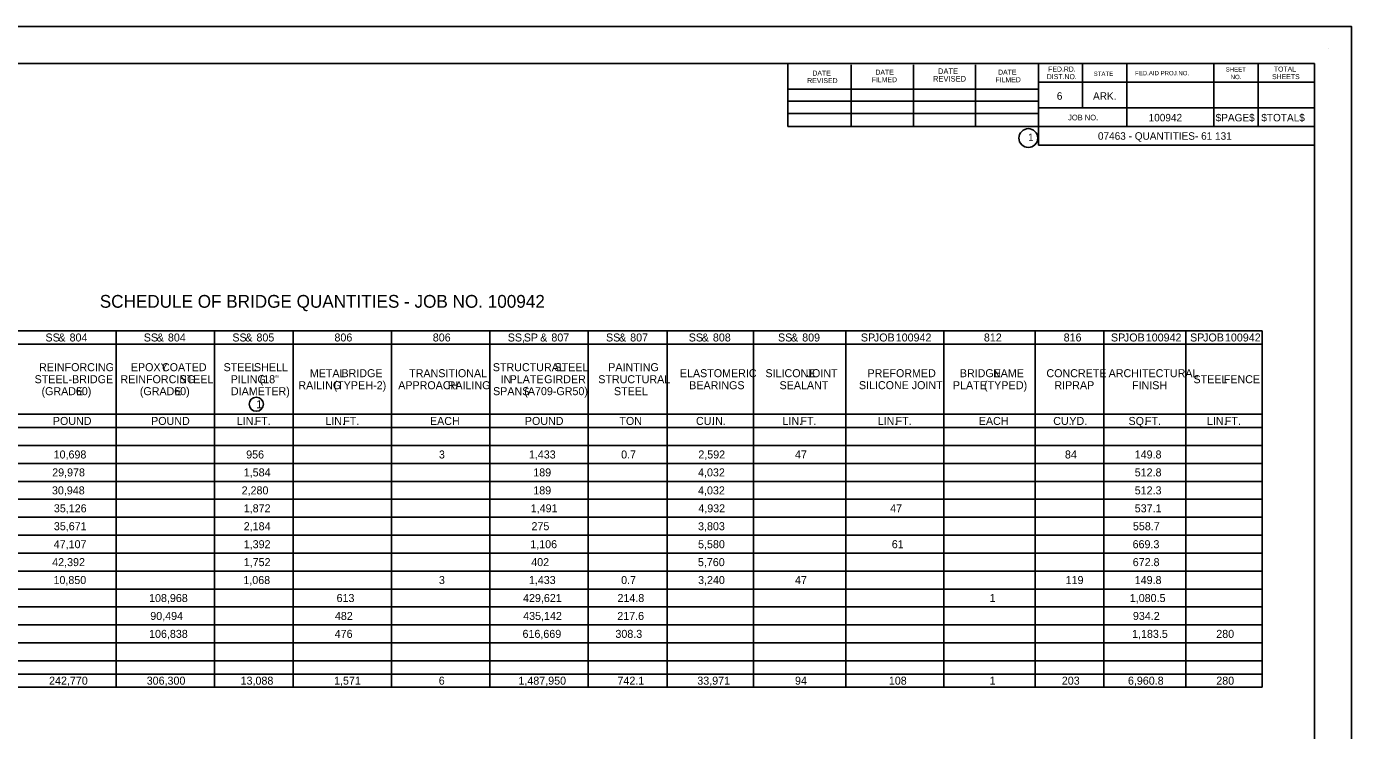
# Model space of a CAD drawing. Extents: x -129 to 14744569, y -102 to 1829048.
# Drawn here: x -115.83 to -95.13, y -90.98 to -79.98 of the extents above; entities that cross this region are included whole.
import ezdxf

# ---------------------------------------------------------------- set-up
doc = ezdxf.new("R2010")
doc.units = 0
for name, color, linetype in [('B_Copy In', 7, 'Continuous'), ('B_Dimensions', 7, 'Continuous'), ('B_Text', 7, 'Continuous'), ('B_Title Text', 7, 'Continuous'), ('R_Border', 7, 'Continuous')]:
    doc.layers.add(name, color=color, linetype=linetype)

msp = doc.modelspace()

# ---------------------------------------------------------------- linework, layer by layer
at = {"layer": 'B_Text'}
msp.add_circle((-112.242, -85.881), 0.11, dxfattribs=at)
at = {"layer": 'B_Title Text'}
for p, q in [((-127.044, -84.735), (-96.527, -84.735)), ((-114.43, -90.304), (-114.43, -84.735)), ((-112.895, -90.304), (-112.895, -84.735)), ((-111.664, -90.304), (-111.664, -84.735)), ((-110.128, -90.304), (-110.128, -84.735)), ((-108.593, -90.304), (-108.593, -84.735)), ((-107.057, -90.304), (-107.057, -84.735)), ((-105.826, -90.304), (-105.826, -84.735)), ((-104.473, -90.304), (-104.473, -84.735)), ((-103.035, -90.304), (-103.035, -84.735)), ((-101.5, -90.304), (-101.5, -84.735)), ((-100.074, -90.304), (-100.074, -84.735)), ((-99.001, -90.304), (-99.001, -84.735)), ((-97.721, -90.304), (-97.721, -84.735)), ((-96.527, -90.304), (-96.527, -84.735)), ((-123.071, -84.942), (-96.527, -84.942)), ((-103.035, -86.039), (-103.035, -84.942)), ((-101.5, -86.039), (-101.5, -84.942)), ((-123.071, -86.039), (-96.527, -86.039)), ((-103.035, -86.039), (-101.5, -86.039)), ((-101.5, -86.039), (-96.527, -86.039)), ((-127.044, -86.246), (-96.527, -86.246)), ((-125.485, -86.526), (-96.527, -86.526)), ((-125.485, -86.807), (-96.527, -86.807)), ((-125.485, -87.087), (-96.527, -87.087)), ((-125.485, -87.367), (-96.527, -87.367)), ((-125.485, -87.648), (-96.527, -87.648)), ((-125.485, -87.928), (-96.527, -87.928)), ((-125.485, -88.208), (-96.527, -88.208)), ((-125.485, -88.489), (-96.527, -88.489)), ((-125.485, -88.769), (-96.527, -88.769)), ((-125.485, -89.049), (-96.527, -89.049)), ((-125.485, -89.329), (-96.527, -89.329)), ((-125.485, -89.61), (-96.527, -89.61)), ((-127.044, -89.89), (-96.527, -89.89)), ((-127.044, -90.097), (-96.527, -90.097)), ((-127.044, -90.304), (-96.527, -90.304))]:
    msp.add_line(p, q, dxfattribs=at)
at = {"layer": 'R_Border'}
for p, q in [((-95.492, -80.326), (-95.492, -80.326)), ((-127.618, -80.556), (-95.711, -80.556)), ((-103.937, -81.544), (-103.937, -80.556)), ((-102.951, -81.544), (-102.951, -80.576)), ((-101.975, -81.544), (-101.975, -80.576)), ((-101.007, -81.544), (-101.007, -80.576)), ((-100.021, -80.556), (-100.021, -81.836)), ((-99.337, -80.556), (-99.337, -81.25)), ((-98.643, -80.556), (-98.643, -81.544)), ((-97.285, -80.556), (-97.285, -81.544)), ((-96.591, -80.556), (-96.591, -81.544)), ((-95.711, -101.403), (-95.711, -80.556)), ((-95.711, -80.85), (-100.021, -80.85)), ((-95.711, -80.848), (-95.711, -80.848)), ((-103.937, -80.958), (-100.021, -80.958)), ((-103.937, -81.144), (-100.021, -81.144)), ((-103.937, -81.544), (-103.937, -81.338)), ((-103.937, -81.338), (-100.021, -81.338)), ((-95.711, -81.25), (-100.021, -81.25)), ((-99.725, -81.25), (-95.711, -81.25)), ((-95.711, -81.544), (-103.937, -81.544)), ((-100.021, -81.836), (-95.711, -81.836))]:
    msp.add_line(p, q, dxfattribs=at)
msp.add_lwpolyline([(-129.134, -79.979), (-95.134, -79.979), (-95.134, -101.979), (-129.134, -101.979)], close=True, dxfattribs=at)
msp.add_circle((-100.182, -81.722), 0.147, dxfattribs=at)

# ---------------------------------------------------------------- texts
at = {"layer": 'B_Copy In'}
msp.add_text('07463 - QUANTITIES- 61 131', height=0.11724, dxfattribs=at).set_placement((-99.095, -81.749))
at = {"layer": 'B_Dimensions'}
msp.add_text('1', height=0.125, rotation=360, dxfattribs=at).set_placement((-112.242, -85.944))
at = {"layer": 'B_Text'}
for s, height, p in [('SS', 0.125, (-115.535, -84.901)), (' &', 0.125, (-115.38, -84.901)), (' 804', 0.125, (-115.205, -84.901)), ('SS', 0.125, (-114, -84.901)), (' &', 0.125, (-113.844, -84.901)), (' 804', 0.125, (-113.669, -84.901)), ('SS', 0.125, (-112.616, -84.901)), (' &', 0.125, (-112.461, -84.901)), (' 805', 0.125, (-112.286, -84.901)), ('806', 0.125, (-111.021, -84.901)), ('806', 0.125, (-109.485, -84.901)), ('SS,', 0.125, (-108.314, -84.901)), (' SP', 0.125, (-108.11, -84.901)), (' &', 0.125, (-107.854, -84.901)), (' 807', 0.125, (-107.679, -84.901)), ('SS', 0.125, (-106.779, -84.901)), (' &', 0.125, (-106.623, -84.901)), (' 807', 0.125, (-106.448, -84.901)), ('SS', 0.125, (-105.487, -84.901)), (' &', 0.125, (-105.331, -84.901)), (' 808', 0.125, (-105.156, -84.901)), ('SS', 0.125, (-104.092, -84.901)), (' &', 0.125, (-103.936, -84.901)), (' 809', 0.125, (-103.761, -84.901)), ('SP', 0.125, (-102.798, -84.901)), (' JOB', 0.125, (-102.641, -84.901)), (' 100942', 0.125, (-102.3, -84.901)), ('812', 0.125, (-100.876, -84.901)), ('816', 0.125, (-99.63, -84.901)), ('SP', 0.125, (-98.892, -84.901)), (' JOB', 0.125, (-98.735, -84.901)), (' 100942', 0.125, (-98.394, -84.901)), ('SP', 0.125, (-97.655, -84.901)), (' JOB', 0.125, (-97.498, -84.901)), (' 100942', 0.125, (-97.157, -84.901)), ('REINFORCING', 0.125, (-115.636, -85.365)), ('EPOXY', 0.125, (-114.202, -85.365)), (' COATED', 0.125, (-113.762, -85.365)), ('STEEL', 0.125, (-112.753, -85.365)), (' SHELL', 0.125, (-112.325, -85.365)), ('STRUCTURAL', 0.125, (-108.547, -85.365)), (' STEEL', 0.125, (-107.63, -85.365)), ('PAINTING', 0.125, (-106.744, -85.365)), ('STEEL-BRIDGE', 0.125, (-115.705, -85.553)), ('REINFORCING', 0.125, (-114.364, -85.553)), (' STEEL', 0.125, (-113.488, -85.553)), ('PILING', 0.125, (-112.642, -85.553)), (' (18"', 0.125, (-112.236, -85.553)), ('METAL', 0.125, (-111.406, -85.459)), (' BRIDGE', 0.125, (-110.958, -85.459)), ('TRANSITIONAL', 0.125, (-109.854, -85.459)), ('IN', 0.125, (-108.426, -85.553)), (' PLATE', 0.125, (-108.331, -85.553)), (' GIRDER', 0.125, (-107.791, -85.553)), ('STRUCTURAL', 0.125, (-106.9, -85.553)), ('ELASTOMERIC', 0.125, (-105.625, -85.459)), ('SILICONE', 0.125, (-104.288, -85.459)), (' JOINT', 0.125, (-103.691, -85.459)), ('PREFORMED ', 0.1248, (-102.694, -85.459)), ('BRIDGE', 0.125, (-101.252, -85.459)), (' NAME', 0.125, (-100.781, -85.459)), ('CONCRETE', 0.125, (-99.899, -85.459)), ('ARCHITECTURAL', 0.125, (-98.927, -85.459)), ('STEEL', 0.125, (-97.602, -85.553)), (' FENCE', 0.125, (-97.175, -85.553)), ('(GRADE', 0.125, (-115.597, -85.74)), (' 60)', 0.125, (-115.107, -85.74)), ('(GRADE', 0.125, (-114.061, -85.74)), (' 60)', 0.125, (-113.571, -85.74)), ('DIAMETER)', 0.125, (-112.638, -85.74)), ('RAILING', 0.125, (-111.585, -85.647)), (' (TYPE', 0.125, (-111.081, -85.647)), (' H-2)', 0.125, (-110.584, -85.647)), ('APPROACH', 0.125, (-110.025, -85.647)), (' RAILING', 0.125, (-109.299, -85.647)), ('SPANS', 0.125, (-108.543, -85.74)), (' (A709-GR50)', 0.125, (-108.102, -85.74)), ('STEEL', 0.125, (-106.655, -85.74)), ('BEARINGS', 0.125, (-105.479, -85.647)), ('SEALANT', 0.125, (-104.068, -85.647)), ('SILICONE JOINT', 0.1248, (-102.828, -85.646)), ('PLATE', 0.125, (-101.36, -85.647)), (' (TYPE', 0.125, (-100.92, -85.647)), (' D)', 0.125, (-100.423, -85.647)), ('RIPRAP', 0.125, (-99.775, -85.647)), ('FINISH', 0.125, (-98.562, -85.647)), ('POUND', 0.125, (-115.42, -86.205)), ('POUND', 0.125, (-113.885, -86.205)), ('LIN.', 0.125, (-112.547, -86.205)), (' FT.', 0.125, (-112.314, -86.205)), ('LIN.', 0.125, (-111.164, -86.205)), (' FT.', 0.125, (-110.931, -86.205)), ('EACH', 0.125, (-109.529, -86.205)), ('POUND', 0.125, (-108.047, -86.205)), ('TON', 0.125, (-106.57, -86.205)), ('CU.', 0.125, (-105.374, -86.205)), (' IN.', 0.125, (-105.168, -86.205)), ('LIN.', 0.125, (-104.022, -86.205)), (' FT.', 0.125, (-103.789, -86.205)), ('LIN.', 0.125, (-102.535, -86.205)), (' FT.', 0.125, (-102.302, -86.205)), ('EACH', 0.125, (-100.956, -86.205)), ('CU.', 0.125, (-99.793, -86.205)), (' YD.', 0.125, (-99.587, -86.205)), ('SQ.', 0.125, (-98.617, -86.205)), (' FT.', 0.125, (-98.408, -86.205)), ('LIN.', 0.125, (-97.392, -86.205)), (' FT.', 0.125, (-97.159, -86.205)), ('10,698', 0.125, (-115.408, -86.729)), ('956', 0.125, (-112.4, -86.729)), ('3', 0.125, (-109.389, -86.729)), ('1,433', 0.125, (-107.984, -86.729)), ('0.7', 0.125, (-106.543, -86.729)), ('2,592', 0.125, (-105.337, -86.729)), ('47', 0.125, (-103.827, -86.729)), ('84', 0.125, (-99.61, -86.729)), ('149.8', 0.125, (-98.52, -86.729)), ('29,978', 0.125, (-115.43, -87.009)), ('1,584', 0.125, (-112.438, -87.009)), ('189', 0.125, (-107.915, -87.009)), ('4,032', 0.125, (-105.341, -87.009)), ('512.8', 0.125, (-98.52, -87.009)), ('30,948', 0.125, (-115.434, -87.29)), ('2,280', 0.125, (-112.471, -87.29)), ('189', 0.125, (-107.915, -87.29)), ('4,032', 0.125, (-105.341, -87.29)), ('512.3', 0.125, (-98.52, -87.29)), ('35,126', 0.125, (-115.404, -87.57)), ('1,872', 0.125, (-112.438, -87.57)), ('1,491', 0.125, (-107.955, -87.57)), ('4,932', 0.125, (-105.337, -87.57)), ('47', 0.125, (-102.34, -87.57)), ('537.1', 0.125, (-98.52, -87.57)), ('35,671', 0.125, (-115.404, -87.85)), ('2,184', 0.125, (-112.438, -87.85)), ('275', 0.125, (-107.943, -87.85)), ('3,803', 0.125, (-105.341, -87.85)), ('558.7', 0.125, (-98.548, -87.85)), ('47,107', 0.125, (-115.406, -88.131)), ('1,392', 0.125, (-112.438, -88.131)), ('1,106', 0.125, (-107.962, -88.131)), ('5,580', 0.125, (-105.341, -88.131)), ('61', 0.125, (-102.315, -88.131)), ('669.3', 0.125, (-98.553, -88.131)), ('42,392', 0.125, (-115.43, -88.411)), ('1,752', 0.125, (-112.438, -88.411)), ('402', 0.125, (-107.947, -88.411)), ('5,760', 0.125, (-105.343, -88.411)), ('672.8', 0.125, (-98.551, -88.411)), ('10,850', 0.125, (-115.41, -88.691)), ('1,068', 0.125, (-112.444, -88.691)), ('3', 0.125, (-109.389, -88.691)), ('1,433', 0.125, (-107.984, -88.691)), ('0.7', 0.125, (-106.543, -88.691)), ('3,240', 0.125, (-105.341, -88.691)), ('47', 0.125, (-103.827, -88.691)), ('119', 0.125, (-99.599, -88.691)), ('149.8', 0.125, (-98.52, -88.691)), ('108,968', 0.125, (-113.917, -88.972)), ('613', 0.125, (-110.988, -88.972)), ('429,621', 0.125, (-108.075, -88.972)), ('214.8', 0.125, (-106.6, -88.972)), ('1', 0.125, (-100.787, -88.972)), ('1,080.5', 0.125, (-98.597, -88.972)), ('90,494', 0.125, (-113.898, -89.252)), ('482', 0.125, (-111.014, -89.252)), ('435,142', 0.125, (-108.073, -89.252)), ('217.6', 0.125, (-106.603, -89.252)), ('934.2', 0.125, (-98.548, -89.252)), ('106,838', 0.125, (-113.917, -89.532)), ('476', 0.125, (-111.017, -89.532)), ('616,669', 0.125, (-108.083, -89.532)), ('308.3', 0.125, (-106.632, -89.532)), ('1,183.5', 0.125, (-98.561, -89.532)), ('280', 0.125, (-97.246, -89.532)), ('242,770', 0.125, (-115.479, -90.263)), ('306,300', 0.125, (-113.954, -90.263)), ('13,088', 0.125, (-112.487, -90.263)), ('1,571', 0.125, (-111.027, -90.263)), ('6', 0.125, (-109.392, -90.263)), ('1,487,950', 0.125, (-108.147, -90.263)), ('742.1', 0.125, (-106.6, -90.263)), ('33,971', 0.125, (-105.353, -90.263)), ('94', 0.125, (-103.827, -90.263)), ('108', 0.125, (-102.361, -90.263)), ('1', 0.125, (-100.787, -90.263)), ('203', 0.125, (-99.659, -90.263)), ('6,960.8', 0.125, (-98.626, -90.263)), ('280', 0.125, (-97.246, -90.263))]:
    msp.add_text(s, height=height, dxfattribs=at).set_placement(p)
at = {"layer": 'B_Title Text'}
msp.add_text('SCHEDULE OF BRIDGE QUANTITIES - JOB NO. 100942', height=0.19992, dxfattribs=at).set_placement((-114.687, -84.374))
at = {"layer": 'R_Border'}
for s, height, p in [('DATE', 0.0782, (-103.555, -80.747)), ('DATE', 0.0782, (-102.571, -80.732)), ('DATE', 0.0879, (-101.593, -80.722)), ('DATE', 0.0782, (-100.655, -80.732)), ('FED.RD.', 0.0782, (-99.873, -80.684)), ('STATE', 0.0684, (-99.161, -80.752)), ('FED.AID PROJ.NO.', 0.0684, (-98.515, -80.742)), ('SHEET', 0.0684, (-97.099, -80.684)), ('TOTAL', 0.0782, (-96.347, -80.684)), ('REVISED', 0.0782, (-103.636, -80.864)), ('FILMED', 0.0782, (-102.629, -80.85)), ('REVISED', 0.0879, (-101.671, -80.84)), ('FILMED', 0.0782, (-100.695, -80.85)), ('DIST.NO.', 0.0782, (-99.893, -80.802)), ('NO.', 0.0684, (-97.021, -80.802)), ('SHEETS', 0.0782, (-96.375, -80.802)), ('6', 0.117, (-99.737, -81.124)), ('ARK.', 0.1172, (-99.171, -81.124)), ('100942', 0.1172, (-98.303, -81.462)), ('$PAGE$', 0.1172, (-97.256, -81.462)), ('$TOTAL$', 0.1172, (-96.542, -81.462)), ('JOB NO.', 0.0879, (-99.561, -81.446)), ('1', 0.117, (-100.186, -81.769))]:
    msp.add_text(s, height=height, dxfattribs=at).set_placement(p)

doc.saveas('drawing.dxf')
